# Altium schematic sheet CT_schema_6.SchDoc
size 581 x 363 mm
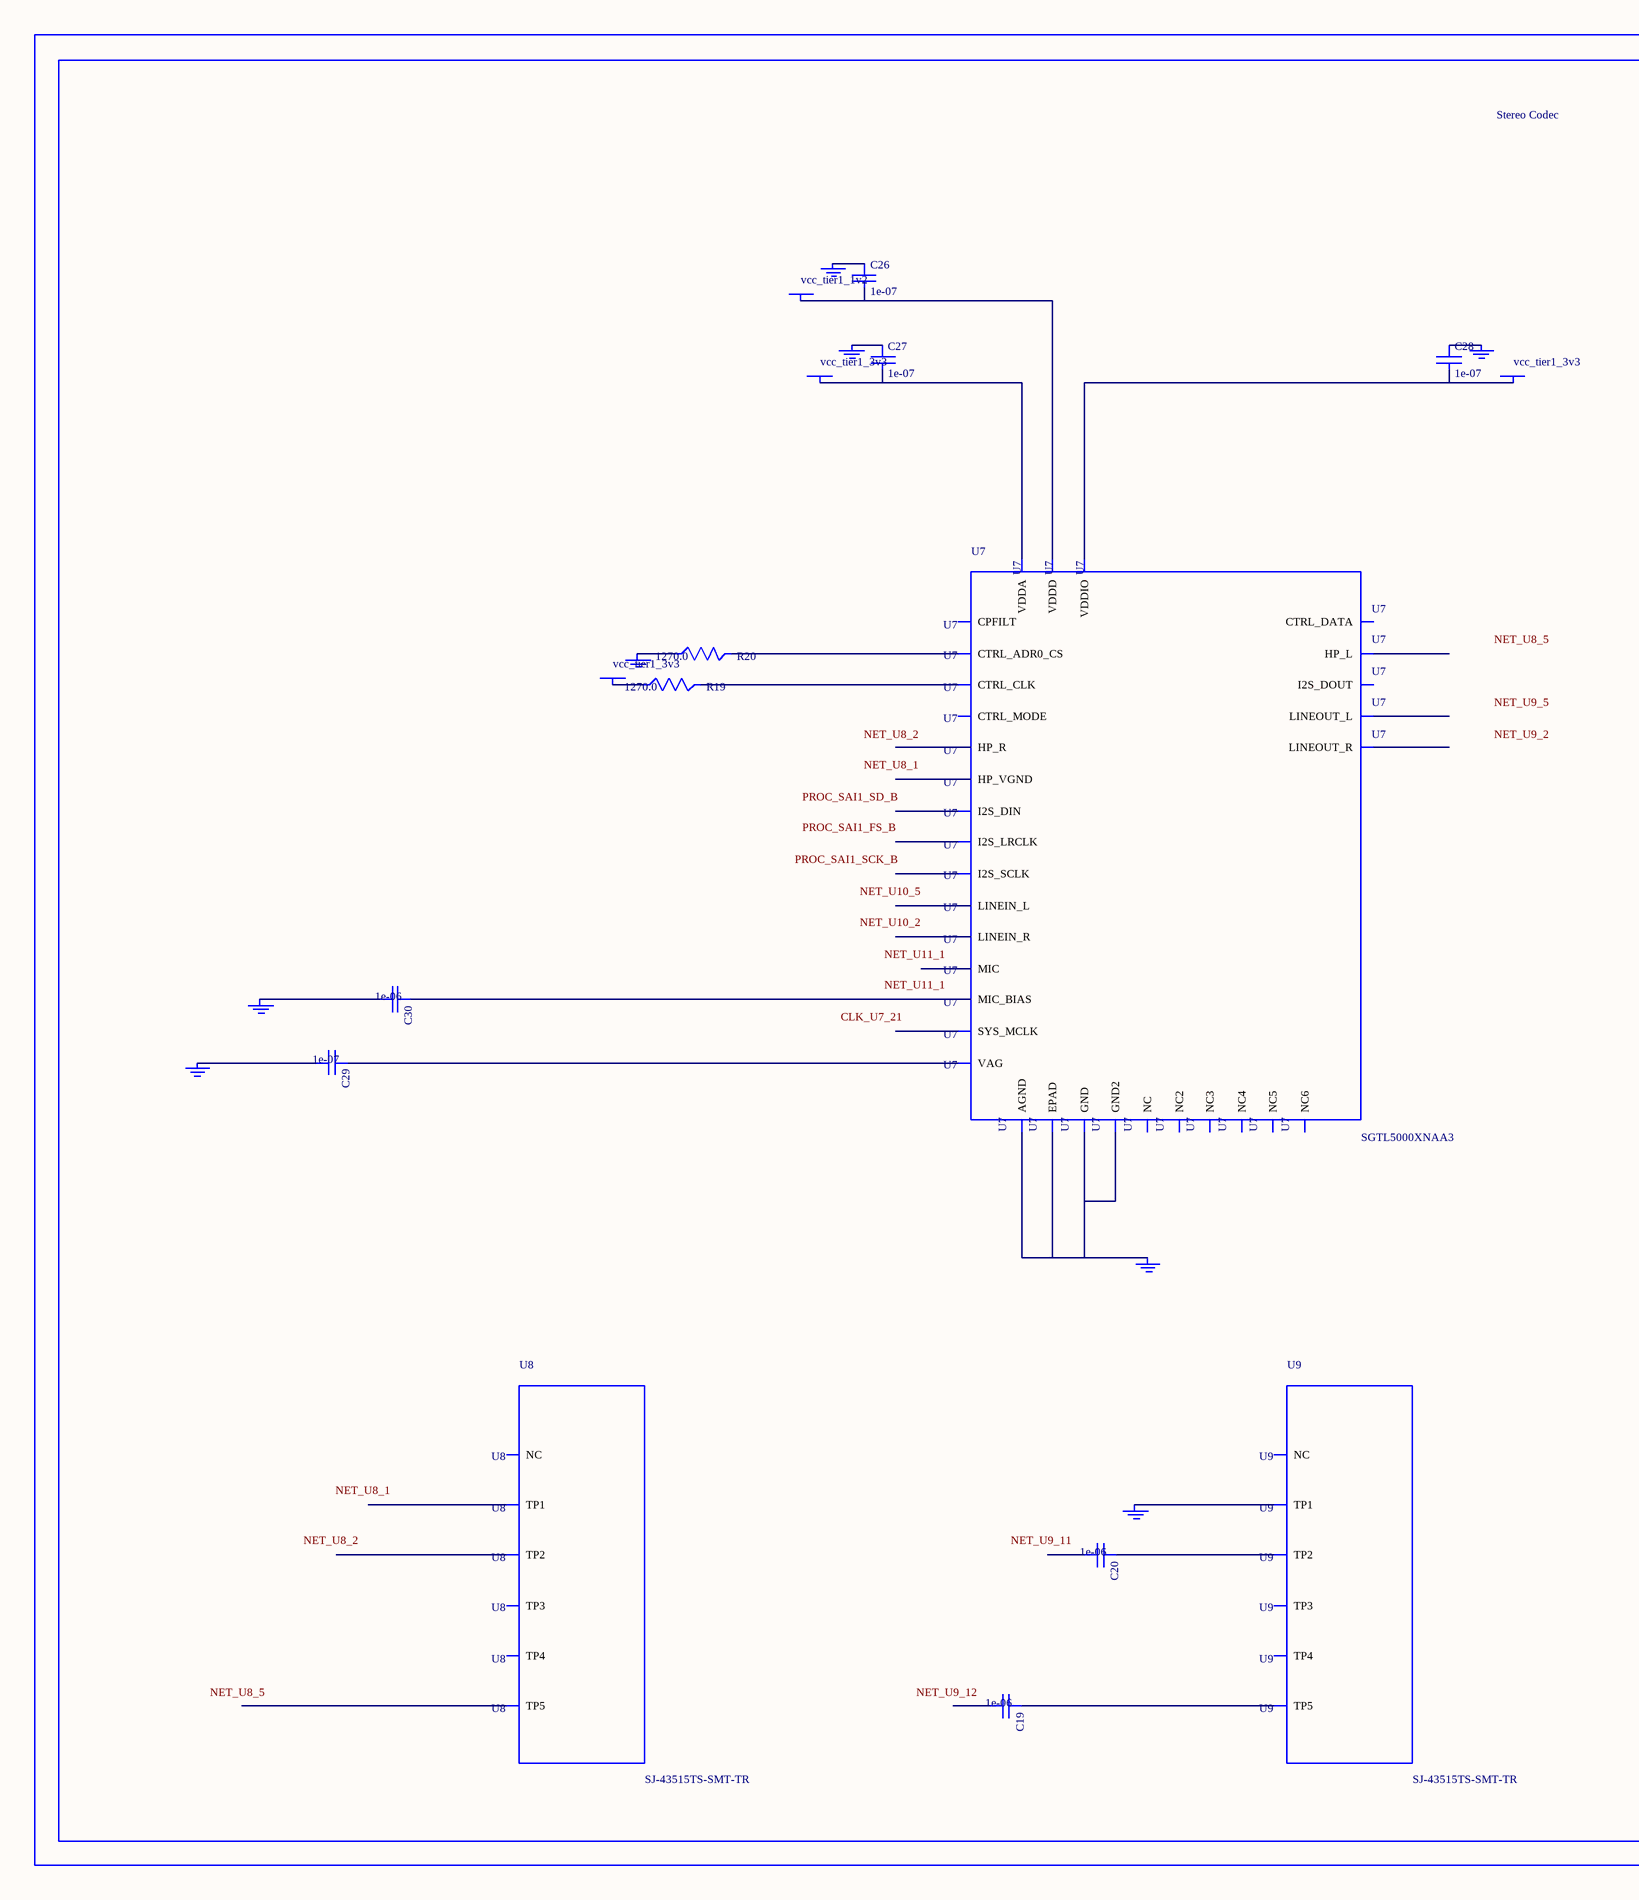
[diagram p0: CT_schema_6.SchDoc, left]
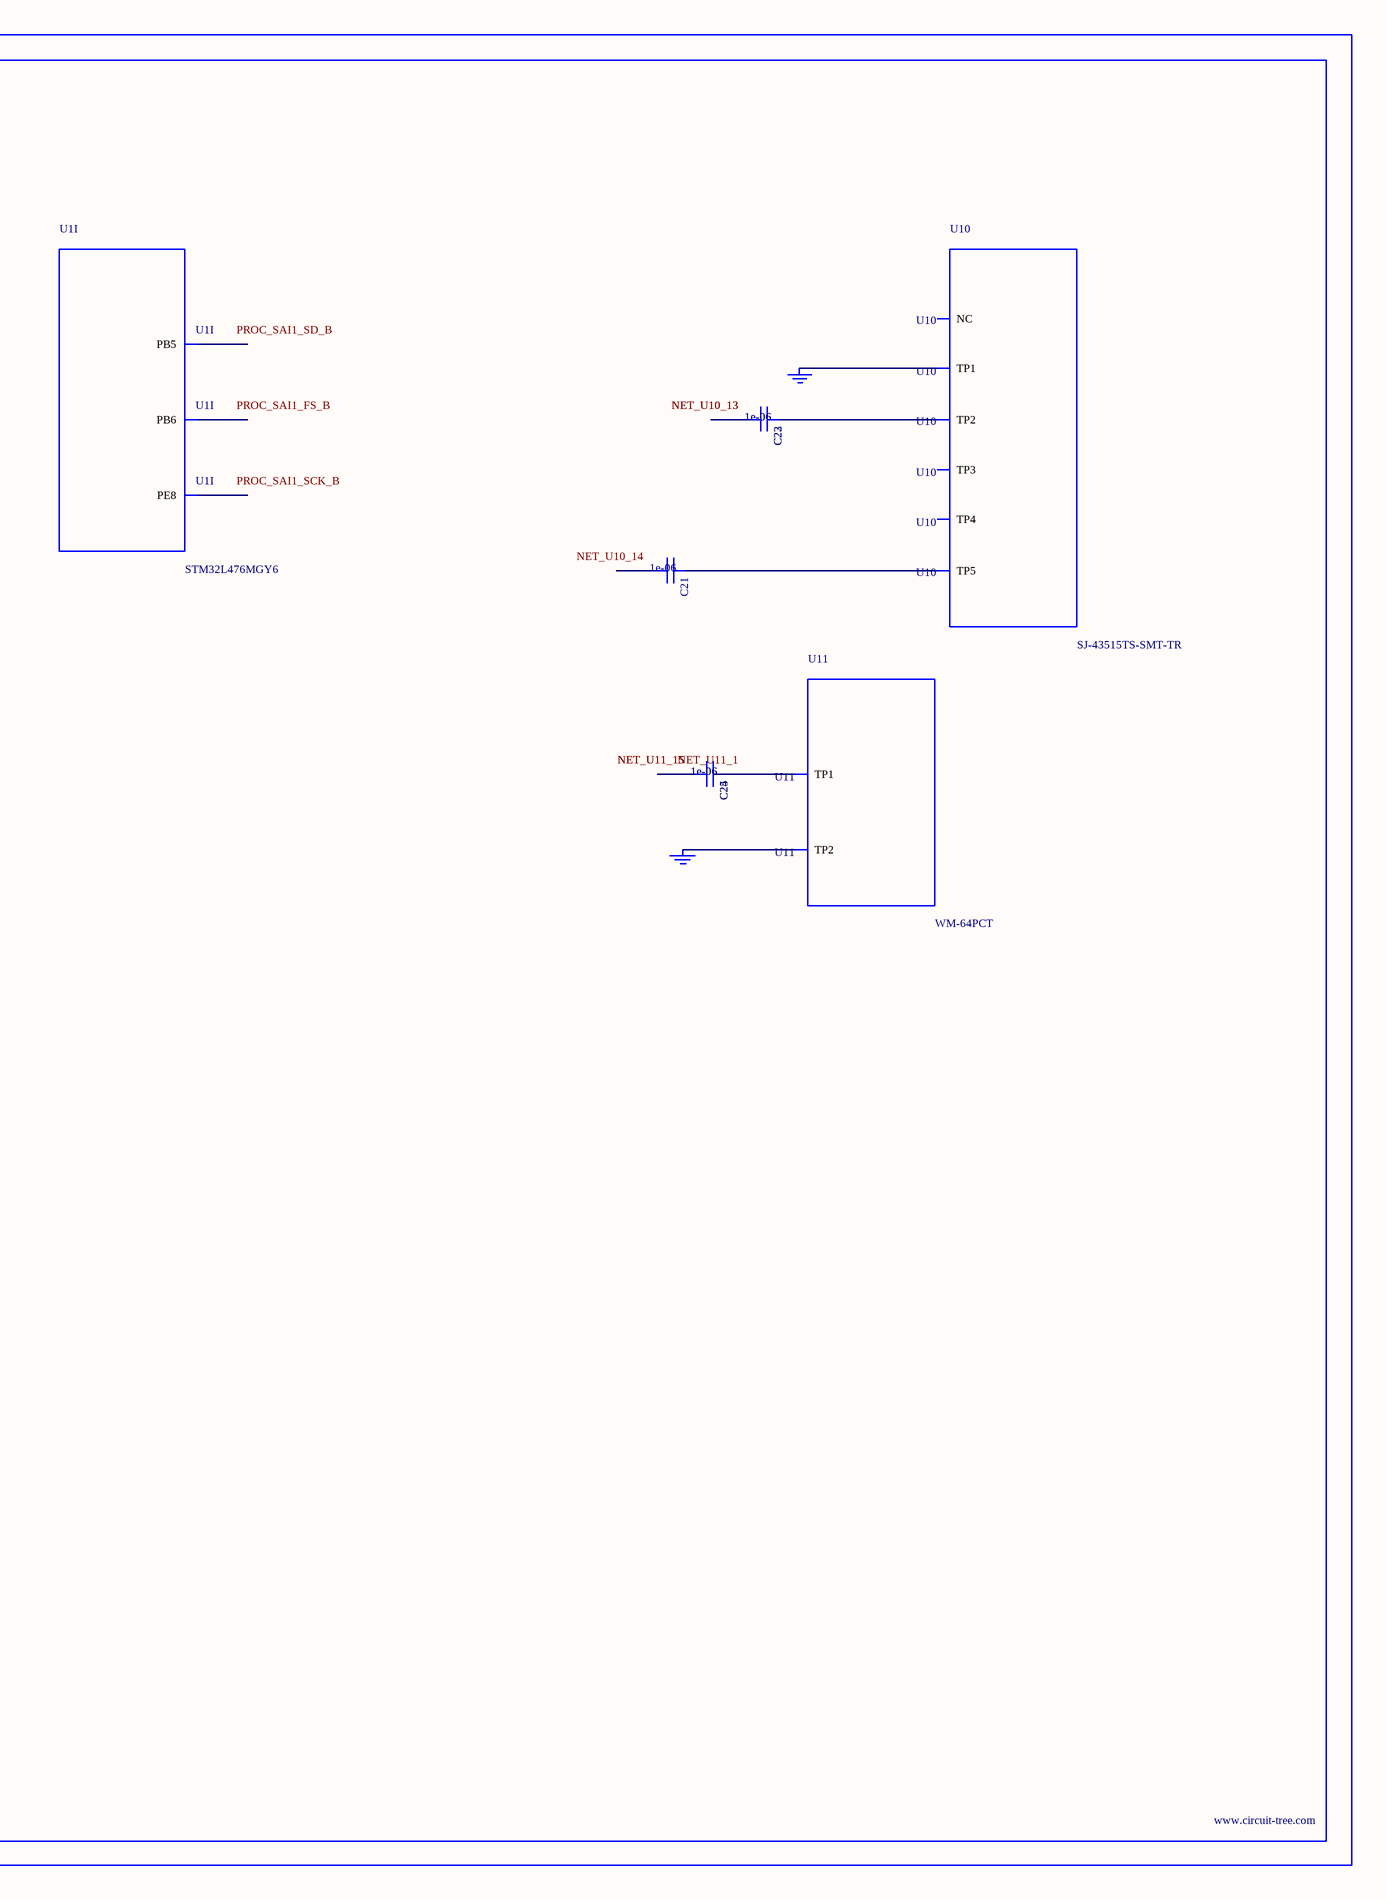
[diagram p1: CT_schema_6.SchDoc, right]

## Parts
BORDER5  (no value)
C19  1e-06  [C0603]
C20  1e-06  [C0603]
C21  1e-06  [C0603]
C22  1e-06  [C0603]
C23  1e-06  [C0603]
C24  1e-06  [C0603]
C25  1e-06  [C0603]
C26  1e-07  [C0402]
C27  1e-07  [C0402]
C28  1e-07  [C0402]
C29  1e-07  [C0402]
C30  1e-06  [C0603]
GND_INSTANCE_5_0  (no value)
GND_INSTANCE_5_1  (no value)
GND_INSTANCE_5_2  (no value)
GND_INSTANCE_5_3  (no value)
GND_INSTANCE_5_4  (no value)
GND_INSTANCE_5_5  (no value)
GND_INSTANCE_5_6  (no value)
GND_INSTANCE_5_7  (no value)
GND_INSTANCE_5_8  (no value)
GND_INSTANCE_5_9  (no value)
GND_INSTANCE_5_10  (no value)
POWER_INSTANCE_5_0  vcc_tier1_3v3
POWER_INSTANCE_5_1  vcc_tier1_3v3
POWER_INSTANCE_5_2  vcc_tier1_3v3
POWER_INSTANCE_5_3  vcc_tier1_1v2
R19  1270.0  [R0603]
R20  1270.0  [R0603]
U1  STM32L476MGY6  [WLCSP81]  (part I of 10)
U7  SGTL5000XNAA3  [QFN-32]
U8  SJ-43515TS-SMT-TR  [SJ-43515TS-SMT-TR]
U9  SJ-43515TS-SMT-TR  [SJ-43515TS-SMT-TR]
U10  SJ-43515TS-SMT-TR  [SJ-43515TS-SMT-TR]
U11  WM-64PCT  [WM-64PC]

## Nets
NetC19_1: C19.1 U9.5(TP5)
NetC20_1: C20.1 U9.2(TP2)
NetC21_1: C21.1 U10.5(TP5)
NetC22_1: C22.1 C23.1 U10.2(TP2)
NetC22_2: C22.2 C23.2
NetC24_1: C24.1 C25.1 U11.1(TP1)
NetC24_2: C24.2 C25.2
NetC26_1: C26.1 GND_INSTANCE_5_5.0(GND)
NetC26_2: C26.2 POWER_INSTANCE_5_3.0(PWR) U7.30(VDDD)
NetC27_1: C27.1 GND_INSTANCE_5_1.0(GND)
NetC27_2: C27.2 POWER_INSTANCE_5_0.0(PWR) U7.5(VDDA)
NetC28_1: C28.1 GND_INSTANCE_5_4.0(GND)
NetC28_2: C28.2 POWER_INSTANCE_5_1.0(PWR) U7.20(VDDIO)
NetC29_1: C29.1 U7.10(VAG)
NetC29_2: C29.2 GND_INSTANCE_5_2.0(GND)
NetC30_1: C30.1 U7.16(MIC_BIAS)
NetC30_2: C30.2 GND_INSTANCE_5_3.0(GND)
NetGND_INSTANCE_5_0_0: GND_INSTANCE_5_0.0(GND) U7.1(GND) U7.3(GND2) U7.7(AGND) U7.EXP(EPAD)
NetGND_INSTANCE_5_6_0: GND_INSTANCE_5_6.0(GND) R20.1
NetGND_INSTANCE_5_7_0: GND_INSTANCE_5_7.0(GND) U9.1(TP1)
NetGND_INSTANCE_5_8_0: GND_INSTANCE_5_8.0(GND) GND_INSTANCE_5_9.0(GND) U10.1(TP1)
NetGND_INSTANCE_5_10_0: GND_INSTANCE_5_10.0(GND) U11.2(TP2)
NetPOWER_INSTANCE_5_2_0: POWER_INSTANCE_5_2.0(PWR) R19.1
NetR19_2: R19.2 U7.29(CTRL_CLK)
NetR20_2: R20.2 U7.31(CTRL_ADR0_CS)

Not connected (* = marked no-connect by the designer): C19 2; C20 2; C21 2; U1 B7(PB6) C7(PB5) F6(PE8); U7 2(HP_R) 4(HP_VGND) 6(HP_L) 8(NC) 9(NC2) 11(LINEOUT_R) 12(LINEOUT_L) 13(LINEIN_R) 14(LINEIN_L) 15(MIC) 17(NC3) 18(CPFILT) 19(NC4) 21(SYS_MCLK) 22(NC5) 23(I2S_LRCLK) 24(I2S_SCLK) 25(I2S_DOUT) 26(I2S_DIN) 27(CTRL_DATA) 28(NC6) 32(CTRL_MODE); U8 1(TP1) 2(TP2) 3(TP3) 4(TP4) 5(TP5) 6(NC); U9 3(TP3) 4(TP4) 6(NC); U10 3(TP3) 4(TP4) 6(NC)

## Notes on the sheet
- Labels drawn without touching a wire or pin: CLK_U7_21, NET_U8_1, NET_U8_2, NET_U8_5, NET_U9_2, NET_U9_5, NET_U9_11, NET_U9_12, NET_U10_2, NET_U10_5, NET_U10_14, NET_U11_1, PROC_SAI1_FS_B, PROC_SAI1_SCK_B, PROC_SAI1_SD_B

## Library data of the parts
BORDER5 = BORDER_PAGE5
C19-C25 C30 = C0603C105K3RACTU
C26-C29 = C0402C104K3RACTU
GND_INSTANCE_5_0-GND_INSTANCE_5_10 = GND
POWER_INSTANCE_5_0-POWER_INSTANCE_5_3 = PWR
R19 R20 = RC0603FR-071K27L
